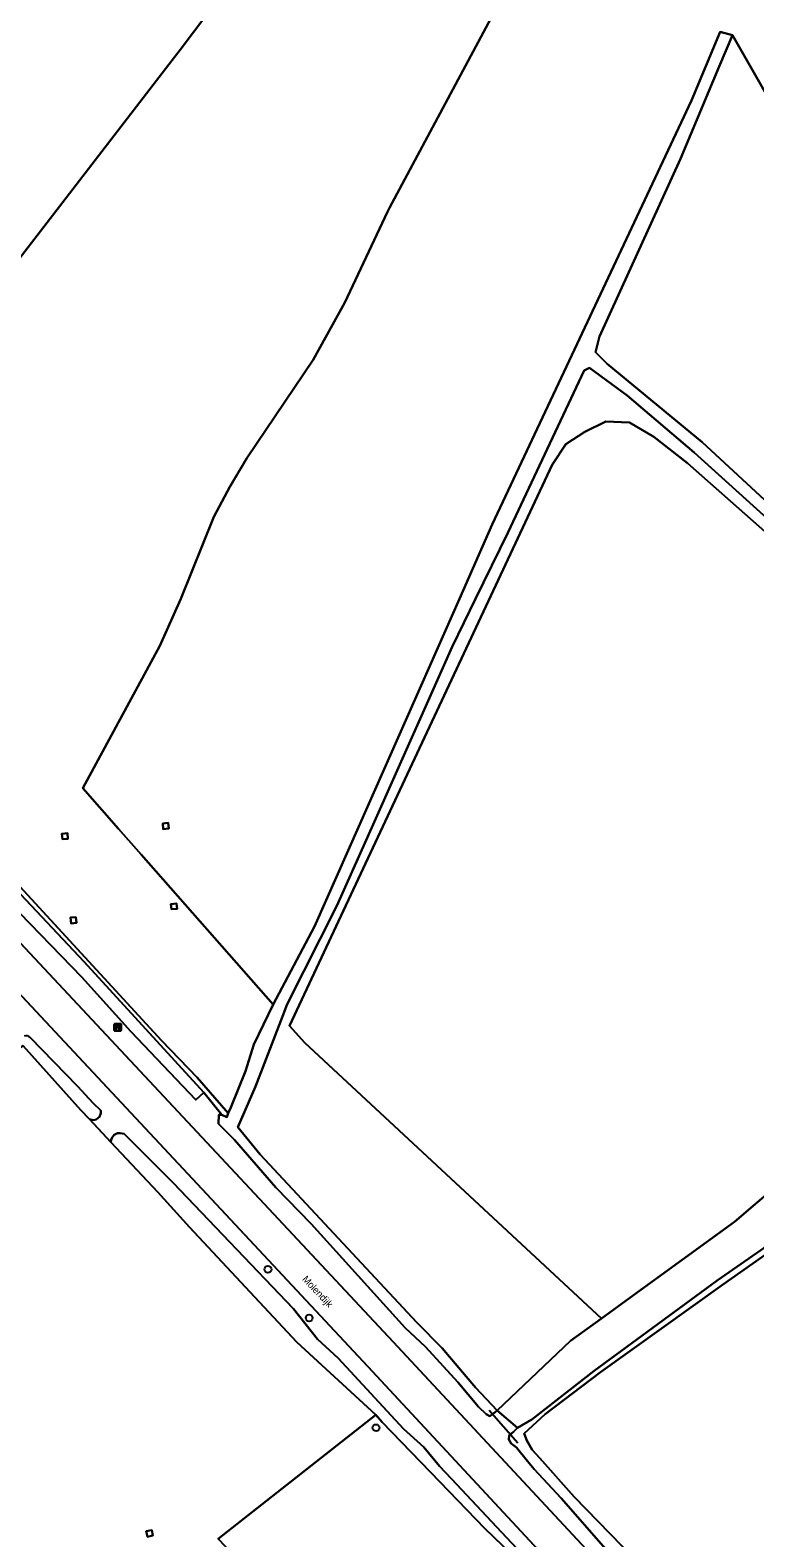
# Model space of a CAD drawing. Extents: x 164494 to 166241, y 382475 to 384495.
# Drawn here: x 165297.4 to 165402.1, y 384114.4 to 384332.1 of the extents above; entities that cross this region are included whole.
import ezdxf

# ---------------------------------------------------------------- set-up
doc = ezdxf.new("R2010")
doc.units = 0
for name, color, linetype in [('IMGEO_Bank', 7, 'Continuous'), ('IMGEO_Boom', 7, 'Continuous'), ('IMGEO_Bouwland', 7, 'Continuous'), ('IMGEO_Duiker', 7, 'Continuous'), ('IMGEO_Grasland_agrarisch', 7, 'Continuous'), ('IMGEO_Grasland_overig', 7, 'Continuous'), ('IMGEO_Groenvoorziening', 7, 'Continuous'), ('IMGEO_Hoogspanningsmast', 7, 'Continuous'), ('IMGEO_Loofbos', 7, 'Continuous'), ('IMGEO_Openbare_ruimte_label', 7, 'Continuous'), ('IMGEO_Rijbaan_lokaal_gesloten', 7, 'Continuous'), ('IMGEO_Waterloop', 7, 'Continuous')]:
    doc.layers.add(name, color=color, linetype=linetype)

msp = doc.modelspace()

# ---------------------------------------------------------------- linework, layer by layer
at = {"layer": 'IMGEO_Bank'}
for p, q in [((165309.57, 384187.74), (165309.57, 384188.58)), ((165309.57, 384188.58), (165309.57, 384187.74)), ((165309.65, 384188.67), (165310.49, 384188.67)), ((165310.49, 384188.67), (165309.65, 384188.67)), ((165309.88, 384188.17), (165309.88, 384188.28)), ((165310.27, 384188.06), (165309.88, 384188.06)), ((165310.21, 384188.28), (165309.93, 384188.28)), ((165309.93, 384188.28), (165309.93, 384188.17)), ((165309.93, 384188.17), (165310.21, 384188.17)), ((165310.22, 384188.17), (165310.22, 384188.28)), ((165310.26, 384188.28), (165310.26, 384188.17)), ((165310.57, 384188.59), (165310.57, 384187.75)), ((165310.57, 384187.75), (165310.57, 384188.59)), ((165310.5, 384187.67), (165309.66, 384187.67)), ((165309.66, 384187.67), (165310.5, 384187.67))]:
    msp.add_line(p, q, dxfattribs=at)
for points in [[(165309.82, 384188.06), (165309.68, 384188.06), (165309.79, 384188.17), (165309.88, 384188.17)], [(165309.88, 384188.28), (165309.79, 384188.28), (165309.79, 384188.45), (165310.35, 384188.45), (165310.35, 384188.28), (165310.27, 384188.28)], [(165309.87, 384188.06), (165309.87, 384187.85), (165309.83, 384187.85), (165309.83, 384188.06)], [(165310.27, 384188.17), (165310.35, 384188.17), (165310.47, 384188.06), (165310.33, 384188.06)], [(165310.32, 384188.06), (165310.32, 384187.85), (165310.28, 384187.85), (165310.28, 384188.06)]]:
    msp.add_lwpolyline(points, dxfattribs=at)
for centre, radius, start, end in [((165309.65, 384188.59), 0.0779, 92.4484, 184.2845), ((165309.65, 384188.59), 0.0779, 92.4484, 184.2845), ((165309.82, 384188.06), 0.00671, 2.8957, 87.1043), ((165309.88, 384188.06), 0.00671, 92.8957, 177.1043), ((165309.88, 384188.28), 0.00671, 2.8957, 87.1043), ((165309.88, 384188.17), 0.00671, 272.8957, 357.1043), ((165309.93, 384188.28), 0.00671, 92.8957, 177.1043), ((165309.93, 384188.17), 0.00671, 182.8957, 267.1043), ((165310.21, 384188.28), 0.00671, 2.8957, 87.1043), ((165310.21, 384188.17), 0.00671, 272.8957, 357.1043), ((165310.27, 384188.28), 0.00671, 92.8957, 177.1043), ((165310.27, 384188.17), 0.00671, 182.8957, 267.1043), ((165310.27, 384188.06), 0.00671, 2.8957, 87.1043), ((165310.33, 384188.06), 0.00671, 92.8957, 177.1043), ((165310.5, 384188.59), 0.0779, 2.4484, 94.2845), ((165310.5, 384188.59), 0.0779, 2.4484, 94.2845), ((165309.65, 384187.74), 0.0779, 182.4484, 274.2845), ((165309.65, 384187.74), 0.0779, 182.4484, 274.2845), ((165310.5, 384187.74), 0.0779, 272.4484, 4.2845), ((165310.5, 384187.74), 0.0779, 272.4484, 4.2845)]:
    msp.add_arc(centre, radius, start, end, dxfattribs=at)
at = {"layer": 'IMGEO_Boom'}
for centre in [(165331.79, 384153.21), (165337.74, 384146.19), (165347.4, 384130.34)]:
    msp.add_circle(centre, 0.489, dxfattribs=at)
at = {"layer": 'IMGEO_Bouwland'}
for points in [[(165408.4, 384257.6), (165393.38, 384271.14), (165383.68, 384279.39), (165378.26, 384283.35), (165377.45, 384283.01), (165366.44, 384259.54), (165361.77, 384250), (165358.39, 384243.09), (165347.17, 384217.89), (165341.76, 384205.72), (165334.57, 384191.51), (165333.88, 384189.72), (165329.97, 384179.63), (165327.44, 384173.72), (165330.68, 384169.78), (165353.31, 384145.55), (165356.95, 384141.82), (165361.77, 384136.17), (165364.91, 384132.82), (165375.51, 384142.87), (165379.98, 384146.12), (165337.12, 384185.91), (165334.92, 384188.38), (165372.87, 384269.39), (165374.81, 384272.33), (165377.55, 384274.13), (165380.58, 384275.62), (165384.03, 384275.46), (165387.55, 384273.42), (165392.42, 384269.63), (165404.83, 384258.64)], [(165404.83, 384258.64), (165392.42, 384269.63), (165387.55, 384273.42), (165384.03, 384275.46), (165380.58, 384275.62), (165377.55, 384274.13), (165374.81, 384272.33), (165372.87, 384269.39), (165334.92, 384188.38), (165337.12, 384185.91), (165379.98, 384146.12), (165384.07, 384149.1), (165399.2, 384160.09), (165405.48, 384165.47)]]:
    msp.add_lwpolyline(points, dxfattribs=at)
at = {"layer": 'IMGEO_Duiker'}
msp.add_lwpolyline([(165367.89, 384128.14), (165363.75, 384132.82)], dxfattribs=at)
at = {"layer": 'IMGEO_Grasland_agrarisch'}
for points in [[(165345.49, 384364.26), (165319.12, 384329.28), (165317.48, 384327.15), (165267.93, 384262.9)], [(165293.19, 384211.49), (165316.39, 384186.25), (165321.54, 384180.91), (165326.06, 384175.76), (165326.4, 384176.6), (165328.54, 384181.84), (165329.77, 384185.67), (165332.53, 384191.47), (165313.46, 384213.11), (165310.21, 384216.8), (165305.04, 384222.67), (165316.17, 384243.24), (165319.21, 384250), (165323.99, 384261.84), (165326.28, 384266.2), (165328.75, 384270.31), (165338.34, 384284.53), (165342.87, 384292.8), (165349.05, 384305.91), (165349.35, 384306.46), (165365.49, 384336.67)], [(165324.58, 384114.29), (165325.92, 384115.35), (165347.39, 384132.2), (165335.97, 384142.71), (165320.44, 384159.32), (165315.88, 384164.36), (165309.08, 384171.59), (165305.99, 384174.88), (165304.75, 384176.21), (165296.41, 384185.48), (165294.17, 384184.07), (165289.31, 384180.6), (165279.06, 384173.47), (165260.79, 384160), (165250.35, 384152.62), (165245.53, 384149.21), (165243.74, 384148.06), (165245.46, 384143.65), (165252.14, 384126.21), (165259.36, 384109.98)]]:
    msp.add_lwpolyline(points, dxfattribs=at)
for points in [[(165426.88, 384242.71), (165429.02, 384244.97), (165425.76, 384248.48), (165430.28, 384276.54), (165430.27, 384276.93), (165430.27, 384279.34), (165429.82, 384281.52), (165428.75, 384283.28), (165407.63, 384316.14), (165398.91, 384331.4), (165397, 384326.87), (165391.37, 384313.56), (165379.68, 384287.88), (165379.09, 384285.64), (165380.81, 384283.93), (165394.5, 384272.63), (165418.99, 384250)], [(165302.8, 384216.17), (165302.89, 384215.38), (165302.09, 384215.3), (165302.01, 384216.09)], [(165318.57, 384206.04), (165318.65, 384205.28), (165317.85, 384205.2), (165317.74, 384205.96)], [(165304.01, 384204.07), (165304.12, 384203.25), (165303.33, 384203.17), (165303.24, 384203.99)], [(165314.21, 384115.39), (165315, 384115.55), (165315.16, 384114.77), (165314.38, 384114.6)]]:
    msp.add_lwpolyline(points, close=True, dxfattribs=at)
at = {"layer": 'IMGEO_Grasland_overig'}
msp.add_lwpolyline([(165233.08, 384275.18), (165232.02, 384274.7), (165255.37, 384250), (165275.8, 384228.59), (165295.27, 384208.19), (165305.21, 384197.62), (165322.53, 384178.74), (165325.13, 384175.54), (165325.83, 384175.2), (165326.06, 384175.76), (165321.54, 384180.91), (165316.39, 384186.25), (165293.19, 384211.49), (165251.87, 384255.44)], close=True, dxfattribs=at)
msp.add_lwpolyline([(165405.48, 384165.47), (165399.2, 384160.09), (165384.07, 384149.1), (165379.98, 384146.12), (165375.51, 384142.87), (165364.91, 384132.82), (165367.85, 384130.32), (165369.91, 384131.53), (165378.91, 384138.55), (165396.68, 384151.59), (165409.79, 384160.68)], dxfattribs=at)
at = {"layer": 'IMGEO_Groenvoorziening'}
for points in [[(165149.92, 384355.97), (165251.27, 384248.07), (165266.44, 384231.9), (165272.49, 384225.43), (165349.9, 384142.75), (165389.4, 384100.28)], [(165392.96, 384088.88), (165346.21, 384139.18), (165268.81, 384221.91), (165262.69, 384228.45)], [(165383.32, 384109.71), (165374.13, 384120.18), (165370.24, 384124.35), (165369.29, 384125.53), (165367.72, 384127.48), (165366.94, 384128.09), (165366.61, 384128.67), (165366.63, 384129.21), (165367.24, 384129.76), (165367.85, 384130.32), (165364.91, 384132.82), (165364.37, 384132.41), (165363.83, 384132.01), (165363.31, 384132.3), (165362.22, 384133.36), (165359.22, 384136.93), (165354.53, 384142.04), (165351.59, 384144.78), (165338.02, 384159.8), (165332.93, 384165.02), (165326.97, 384171.93), (165324.64, 384174.2), (165324.69, 384175.5), (165325.13, 384175.54), (165322.53, 384178.74), (165321.36, 384177.67), (165311.96, 384187.56), (165304.9, 384195.4), (165292.88, 384207.71)], [(165297.43, 384186.7), (165304.28, 384179.68), (165306.55, 384177.22), (165307.64, 384176.13), (165307.62, 384175.74), (165307.46, 384175.23), (165306.95, 384174.83), (165306.6, 384174.74), (165305.99, 384174.88), (165309.08, 384171.59), (165309.12, 384171.92), (165309.26, 384172.26), (165309.56, 384172.65), (165310.03, 384172.86), (165310.43, 384172.86), (165310.99, 384172.79), (165318.08, 384165.69), (165335.46, 384147.52), (165338.93, 384143.15), (165341.91, 384140.37), (165351.37, 384130.2), (165354.29, 384127.52), (165356.55, 384124.82), (165358.3, 384122.95), (165392.45, 384086.58)]]:
    msp.add_lwpolyline(points, dxfattribs=at)
msp.add_lwpolyline([(165356.6, 384122.55), (165348.29, 384131.16), (165347.39, 384132.2), (165325.92, 384115.35), (165324.58, 384114.29), (165348.61, 384089.13), (165369.93, 384109.25), (165369.5, 384109.69), (165363.14, 384115.79)], close=True, dxfattribs=at)
msp.add_arc((165296.85, 384186.14), 0.799, 44.3556, 111.0539, dxfattribs=at)
at = {"layer": 'IMGEO_Hoogspanningsmast'}
for points in [[(165302.01, 384216.09), (165302.09, 384215.3), (165302.89, 384215.38), (165302.8, 384216.17)], [(165316.59, 384217.58), (165316.67, 384216.78), (165317.46, 384216.86), (165317.38, 384217.66)], [(165318.65, 384205.28), (165318.57, 384206.04), (165317.74, 384205.96), (165317.85, 384205.2)], [(165303.33, 384203.17), (165304.12, 384203.25), (165304.01, 384204.07), (165303.24, 384203.99)], [(165314.21, 384115.39), (165314.38, 384114.6), (165315.16, 384114.77), (165315, 384115.55)]]:
    msp.add_lwpolyline(points, close=True, dxfattribs=at)
at = {"layer": 'IMGEO_Loofbos'}
for points in [[(165257.7, 384359.88), (165238.75, 384323.39), (165229.45, 384306.17), (165221.72, 384299.42), (165215.52, 384292.35), (165217.95, 384289.68), (165231.34, 384300.16), (165248.84, 384282.34), (165267.93, 384262.9), (165317.48, 384327.15), (165319.12, 384329.28), (165345.49, 384364.26)], [(165365.49, 384336.67), (165349.35, 384306.46), (165349.05, 384305.91), (165342.87, 384292.8), (165338.34, 384284.53), (165328.75, 384270.31), (165326.28, 384266.2), (165323.99, 384261.84), (165319.21, 384250), (165316.17, 384243.24), (165305.04, 384222.67), (165310.21, 384216.8), (165313.46, 384213.11), (165332.53, 384191.47), (165338.52, 384202.73), (165345.06, 384217.5), (165359.45, 384250), (165364.2, 384260.75), (165375.7, 384285.21), (165392.98, 384321.96), (165397.13, 384331.86), (165398.91, 384331.4), (165407.63, 384316.14)], [(165462.24, 384108.19), (165456.3, 384114.59), (165449.75, 384122.32), (165443.62, 384129.92), (165436.54, 384138.19), (165434.69, 384140.9), (165431.82, 384145.09), (165426.11, 384155.98), (165419.9, 384165.79), (165410.63, 384160.2), (165397.44, 384150.98), (165379.84, 384138.36), (165371.85, 384132.31), (165368.79, 384129.53), (165369.19, 384128.51), (165369.98, 384127.15), (165371.06, 384125.95), (165376.05, 384120.38), (165393.36, 384102.54)]]:
    msp.add_lwpolyline(points, dxfattribs=at)
msp.add_lwpolyline([(165317.38, 384217.66), (165317.46, 384216.86), (165316.67, 384216.78), (165316.59, 384217.58)], close=True, dxfattribs=at)
at = {"layer": 'IMGEO_Rijbaan_lokaal_gesloten'}
for points in [[(165272.49, 384225.43), (165266.44, 384231.9), (165262.69, 384228.45), (165268.81, 384221.91), (165346.21, 384139.18), (165392.96, 384088.88)], [(165398.79, 384090.55), (165396.29, 384093.01), (165389.4, 384100.28), (165349.9, 384142.75), (165272.49, 384225.43)]]:
    msp.add_lwpolyline(points, dxfattribs=at)
at = {"layer": 'IMGEO_Waterloop'}
for points in [[(165418.99, 384250), (165394.5, 384272.63), (165380.81, 384283.93), (165379.09, 384285.64), (165379.68, 384287.88), (165391.37, 384313.56), (165397, 384326.87), (165398.91, 384331.4), (165397.13, 384331.86), (165392.98, 384321.96), (165375.7, 384285.21), (165364.2, 384260.75), (165359.45, 384250), (165345.06, 384217.5), (165338.52, 384202.73), (165332.53, 384191.47), (165329.77, 384185.67), (165328.54, 384181.84), (165326.4, 384176.6), (165326.06, 384175.76), (165325.83, 384175.2), (165325.13, 384175.54), (165324.69, 384175.5), (165324.64, 384174.2), (165326.97, 384171.93), (165332.93, 384165.02), (165338.02, 384159.8), (165351.59, 384144.78), (165354.53, 384142.04), (165359.22, 384136.93), (165362.22, 384133.36), (165363.31, 384132.3), (165363.83, 384132.01), (165364.37, 384132.41), (165364.91, 384132.82), (165361.77, 384136.17), (165356.95, 384141.82), (165353.31, 384145.55), (165330.68, 384169.78), (165327.44, 384173.72), (165329.97, 384179.63), (165333.88, 384189.72), (165334.57, 384191.51), (165341.76, 384205.72), (165347.17, 384217.89), (165358.39, 384243.09), (165361.77, 384250), (165366.44, 384259.54), (165377.45, 384283.01), (165378.26, 384283.35), (165383.68, 384279.39), (165393.38, 384271.14), (165408.4, 384257.6)], [(165304.28, 384179.68), (165297.43, 384186.7)], [(165296.32, 384185.55), (165296.41, 384185.48), (165304.75, 384176.21), (165305.99, 384174.88), (165306.6, 384174.74), (165306.95, 384174.83), (165307.46, 384175.23), (165307.62, 384175.74), (165307.64, 384176.13), (165306.55, 384177.22), (165304.28, 384179.68)], [(165318.08, 384165.69), (165310.99, 384172.79), (165310.43, 384172.86), (165310.03, 384172.86), (165309.56, 384172.65), (165309.26, 384172.26), (165309.12, 384171.92), (165309.08, 384171.59), (165315.88, 384164.36), (165320.44, 384159.32), (165335.97, 384142.71), (165347.39, 384132.2), (165348.29, 384131.16), (165356.6, 384122.55), (165363.14, 384115.79), (165369.5, 384109.69), (165369.93, 384109.25), (165382.45, 384096.31), (165388.41, 384089.95), (165391.68, 384085.73)], [(165439.58, 384138.15), (165437.4, 384141.53), (165433.76, 384147.17), (165424.62, 384163.25), (165422.16, 384166.2), (165420.97, 384167.63), (165409.79, 384160.68), (165396.68, 384151.59), (165378.91, 384138.55), (165369.91, 384131.53), (165367.85, 384130.32), (165367.24, 384129.76), (165366.63, 384129.21), (165366.61, 384128.67), (165366.94, 384128.09), (165367.72, 384127.48), (165369.29, 384125.53), (165370.24, 384124.35), (165374.13, 384120.18), (165383.32, 384109.71), (165388.69, 384104.19), (165390.57, 384101.8), (165394.69, 384097.69)], [(165392.45, 384086.58), (165358.3, 384122.95), (165356.55, 384124.82), (165354.29, 384127.52), (165351.37, 384130.2), (165341.91, 384140.37), (165338.93, 384143.15), (165335.46, 384147.52), (165318.08, 384165.69)], [(165396.43, 384098.96), (165393.36, 384102.54), (165376.05, 384120.38), (165371.06, 384125.95), (165369.98, 384127.15), (165369.19, 384128.51), (165368.79, 384129.53), (165371.85, 384132.31), (165379.84, 384138.36), (165397.44, 384150.98), (165410.63, 384160.2), (165419.9, 384165.79), (165426.11, 384155.98), (165431.82, 384145.09), (165434.69, 384140.9), (165436.54, 384138.19), (165443.62, 384129.92), (165449.75, 384122.32), (165456.3, 384114.59), (165462.24, 384108.19)]]:
    msp.add_lwpolyline(points, dxfattribs=at)
msp.add_lwpolyline([(165232.02, 384274.7), (165220.11, 384287.31), (165219.02, 384286.4), (165252.93, 384250), (165271.99, 384229.76), (165274.42, 384227.27), (165282.82, 384218.63), (165291.99, 384208.63), (165292.88, 384207.71), (165304.9, 384195.4), (165311.96, 384187.56), (165321.36, 384177.67), (165322.53, 384178.74), (165305.21, 384197.62), (165295.27, 384208.19), (165275.8, 384228.59), (165255.37, 384250)], close=True, dxfattribs=at)
msp.add_arc((165296.85, 384186.14), 0.799, 44.3556, 111.0539, dxfattribs=at)

# ---------------------------------------------------------------- texts
at = {"layer": 'IMGEO_Openbare_ruimte_label'}
msp.add_text('Molendijk', height=1, rotation=313.0949, dxfattribs=at).set_placement((165336.68, 384151.73))

doc.saveas('drawing.dxf')
